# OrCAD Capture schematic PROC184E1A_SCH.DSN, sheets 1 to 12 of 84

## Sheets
1 07. PDN: title: PDN; rev: E1; note: PROC141_SCH
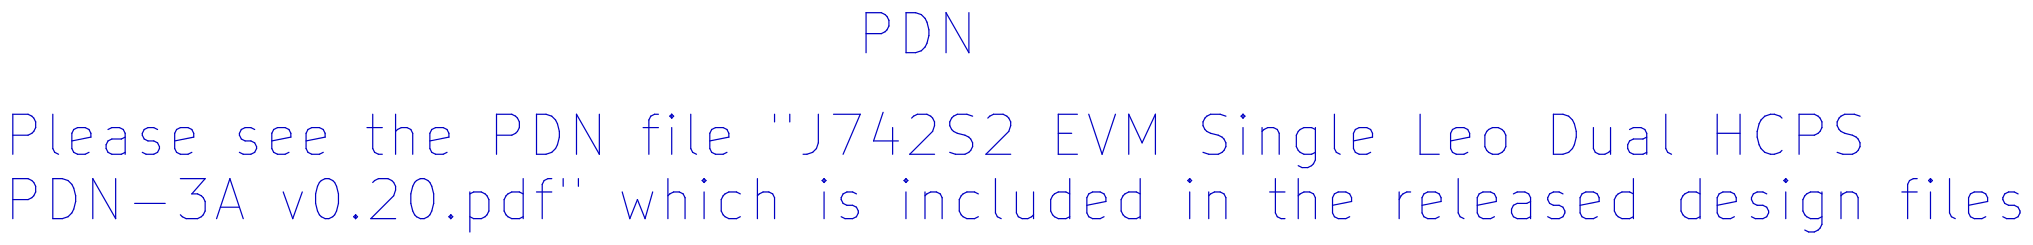
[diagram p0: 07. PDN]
2 03. REVISION HISTORY #2: title: REVISION HISTORY; note: PROC184_SCH
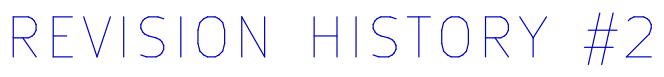
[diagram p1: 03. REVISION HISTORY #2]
3 09. I2C TABLE: title: REVISION HISTORY; note: PROC184_SCH
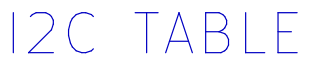
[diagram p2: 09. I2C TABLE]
4 01. TABLE OF CONTENTS: title: TABLE OF CONTENTS; note: PROC184_SCH
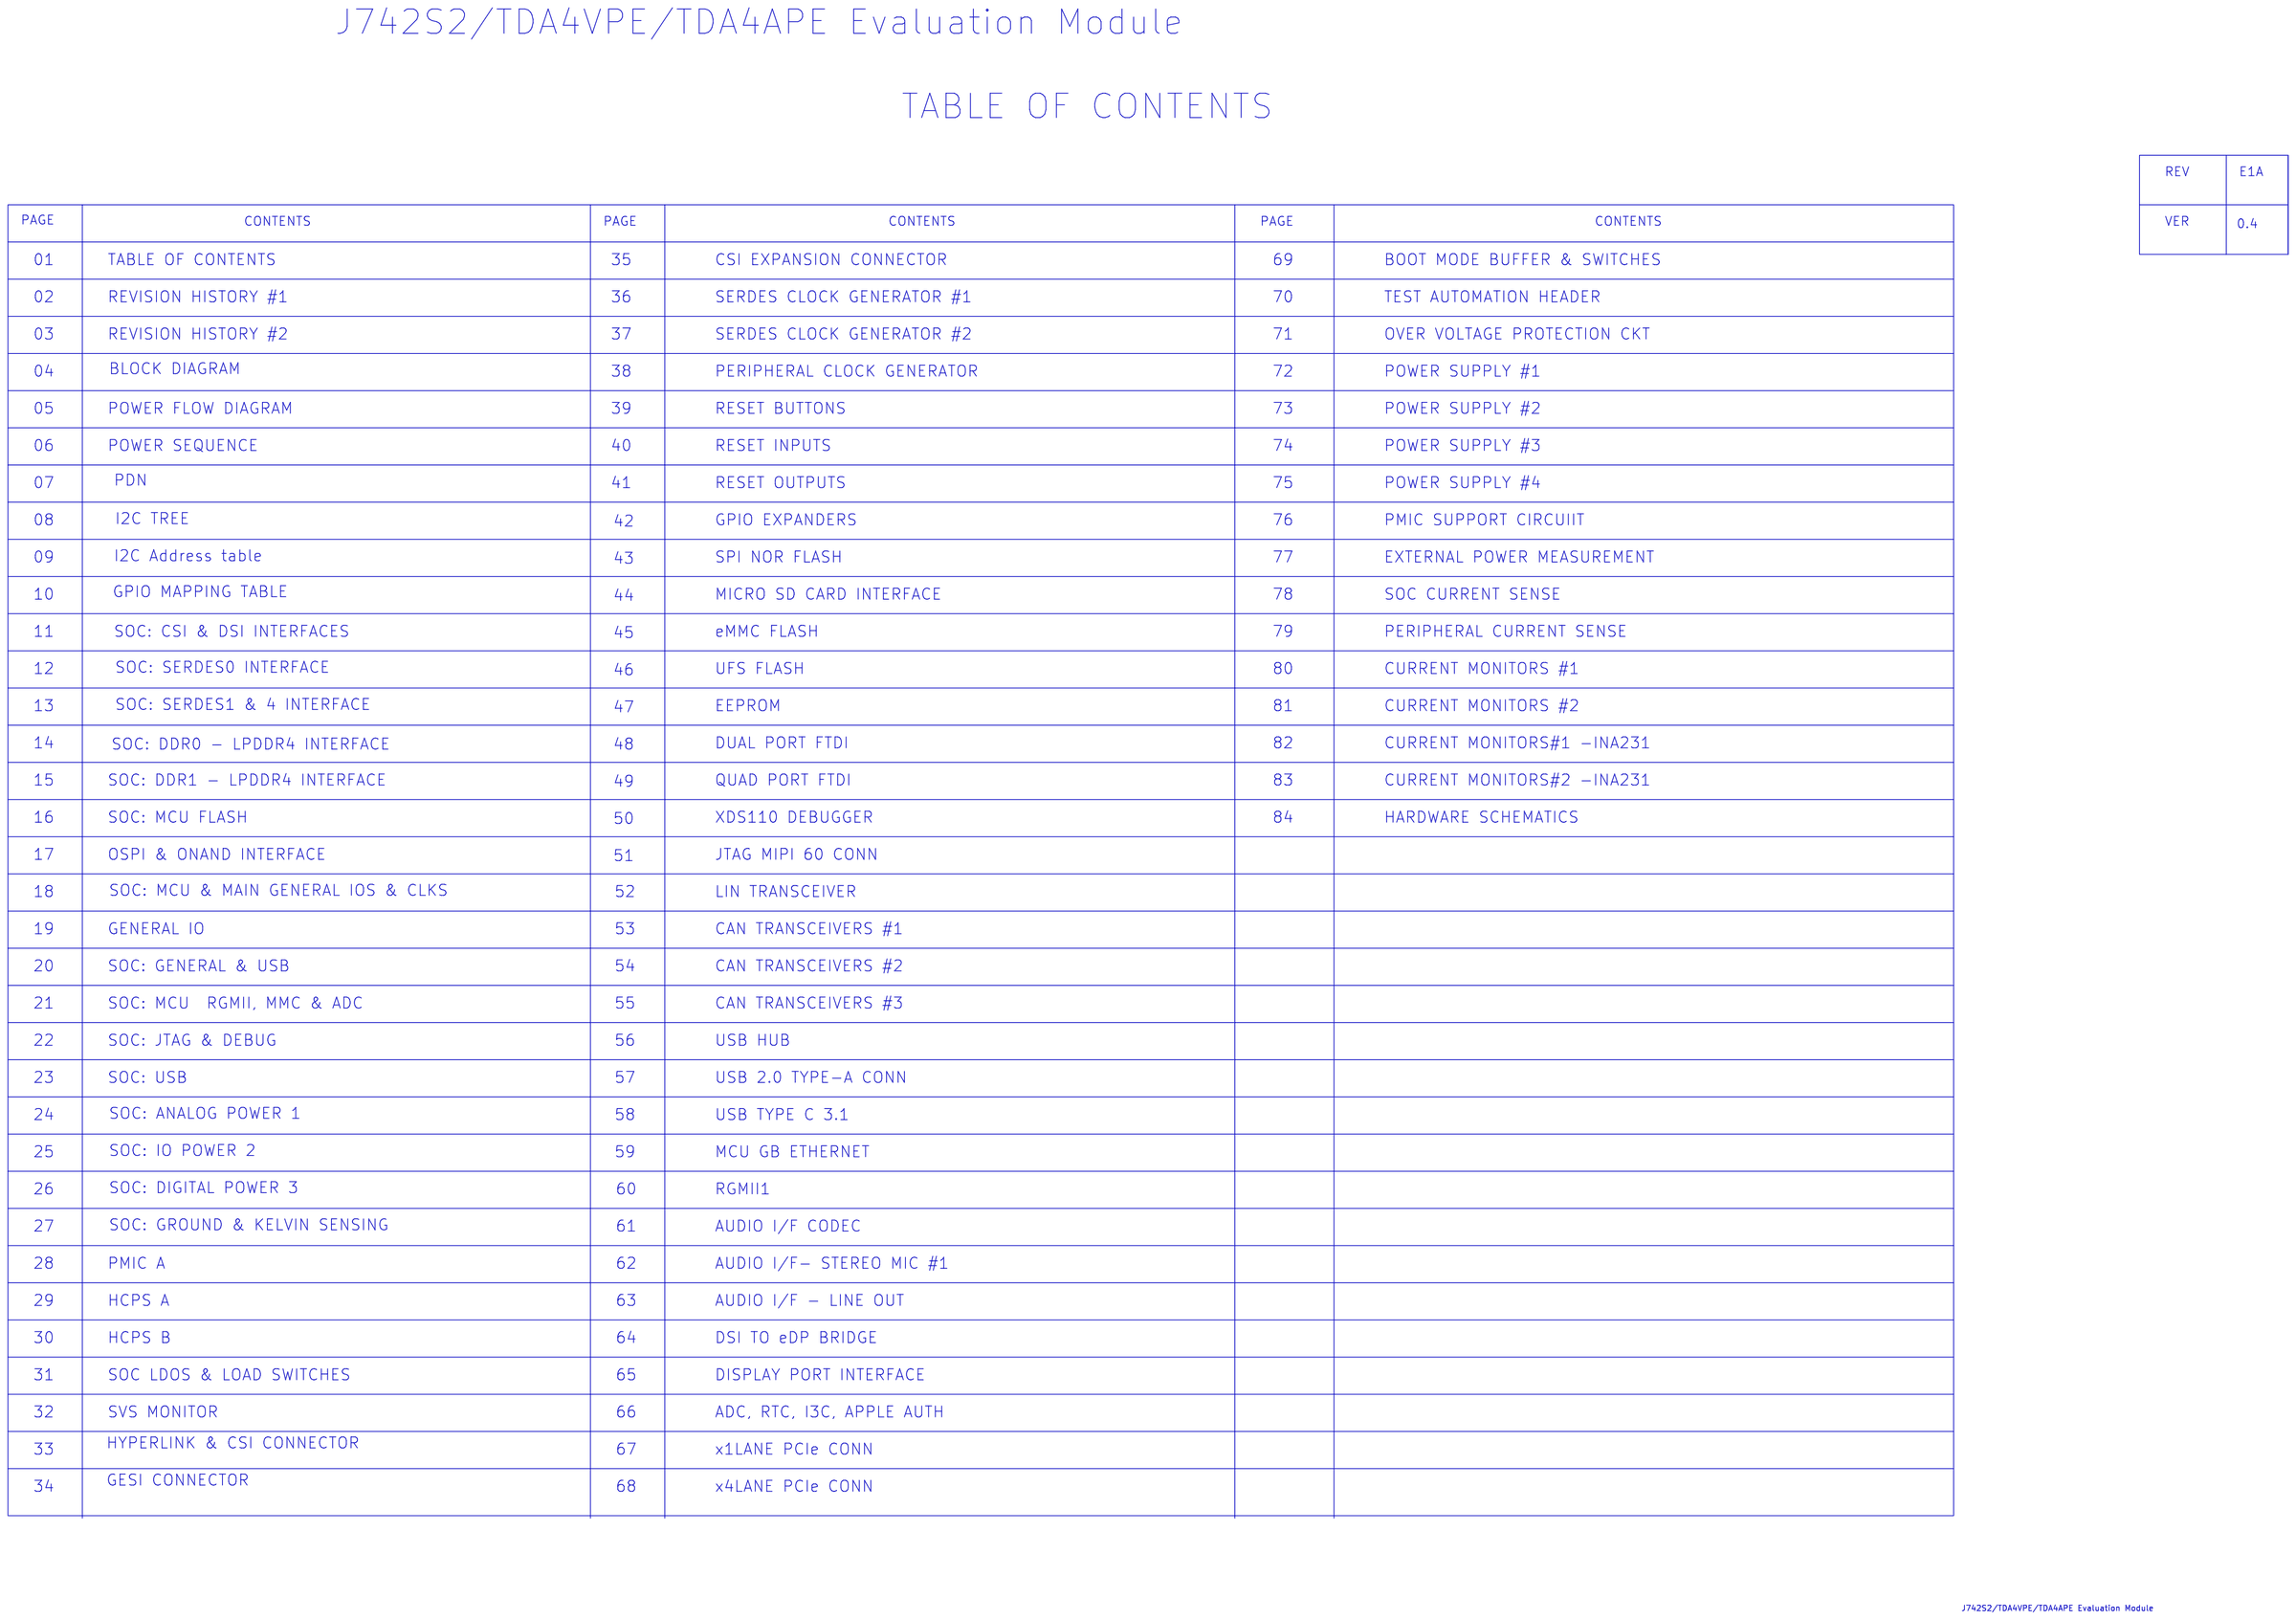
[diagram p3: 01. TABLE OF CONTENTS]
5 02. REVISION HISTORY #1: title: REVISION HISTORY; note: PROC184_SCH
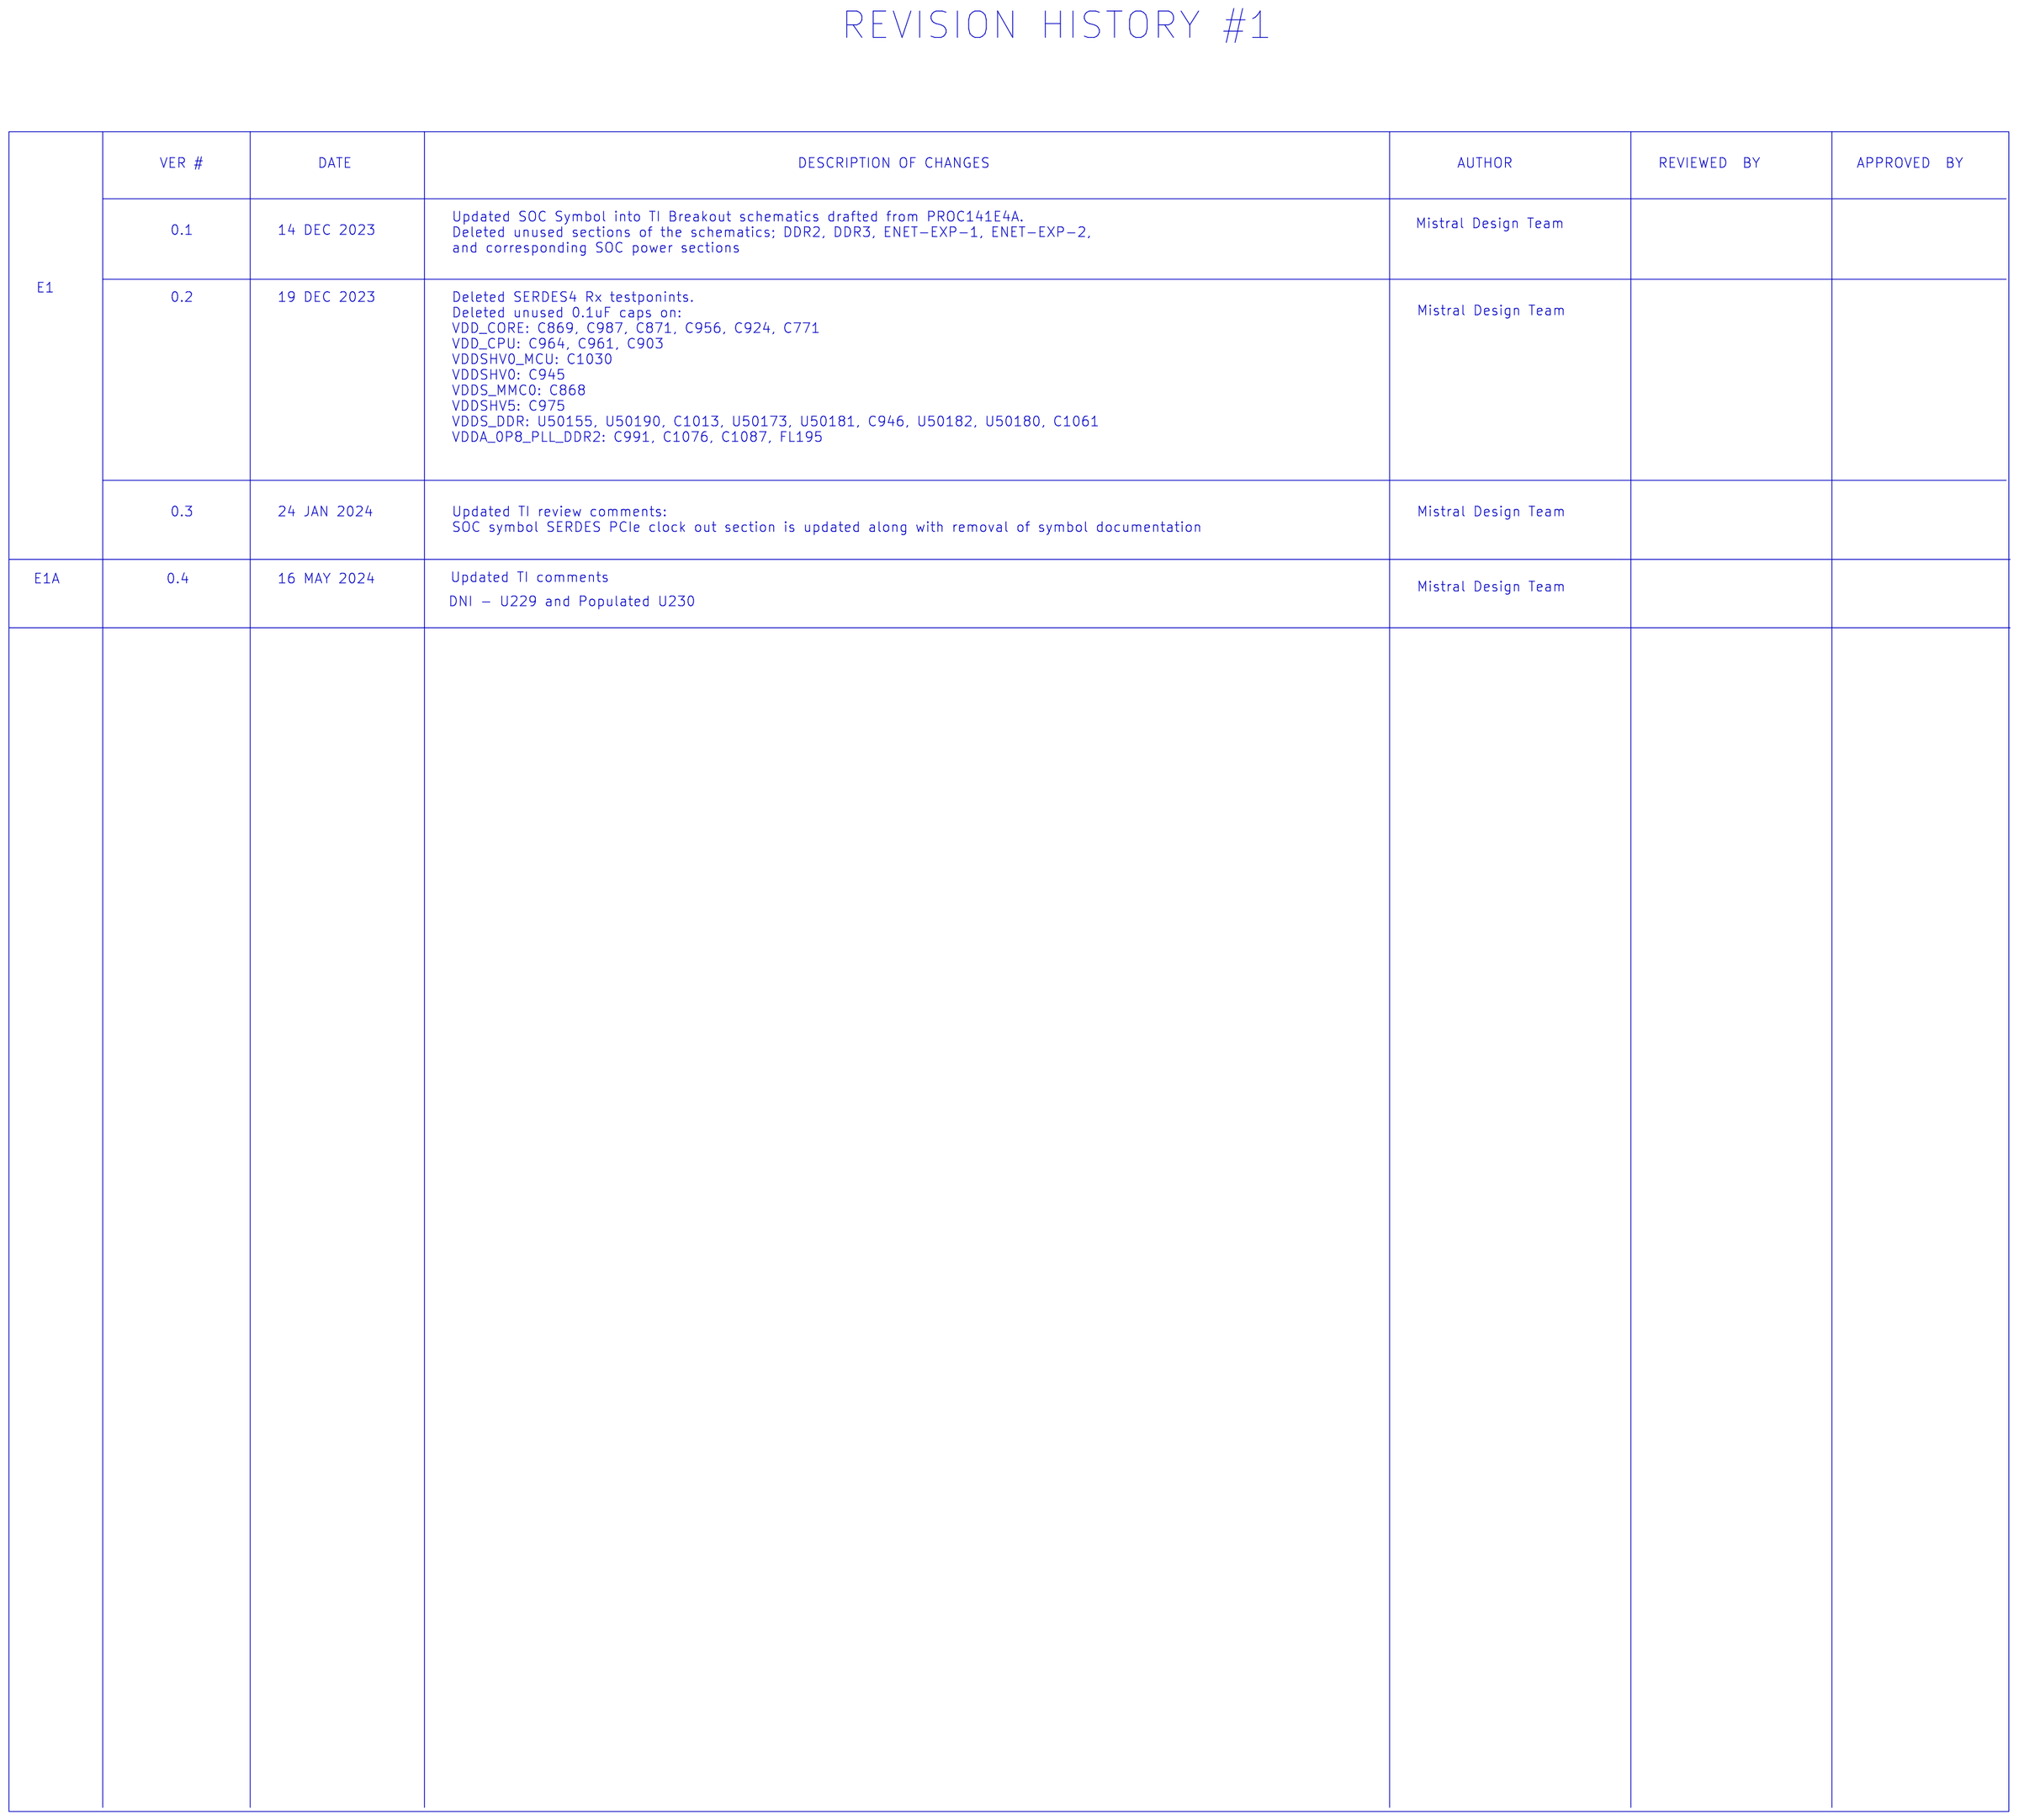
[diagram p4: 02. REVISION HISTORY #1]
6 04. BLOCK_DIAGRAM: title: BLOCK DIAGRAM; note: PROC184_SCH
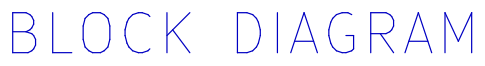
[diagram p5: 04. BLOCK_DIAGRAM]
7 05. POWER FLOW DIAGRAM: title: POWER FLOW DIAGRAM; note: PROC184_SCH
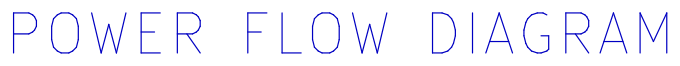
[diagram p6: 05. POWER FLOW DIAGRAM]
8 06. POWER SEQUENCE: title: POWER SEQUENCE; note: PROC184_SCH
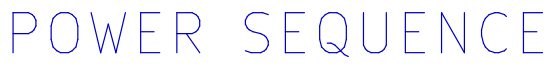
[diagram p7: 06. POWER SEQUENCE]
9 08. I2C TREE: title: I2C TREE; note: PROC184_SCH
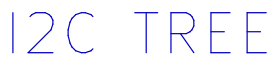
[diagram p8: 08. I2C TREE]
10 10. GPIO MAPPING TABLE: title: GPIO  EXPANDER MAP/TABLE; note: PROC184_SCH
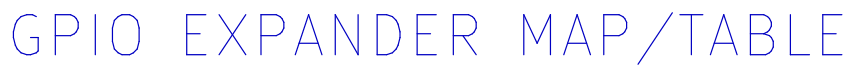
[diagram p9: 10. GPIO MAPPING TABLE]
11 11. SOC CSI & DSI IF: size C; title: CSI & DSI INTERFACE; company: TEXAS INSTRUMENTS INCORPORATED; note: PROC184_SCH
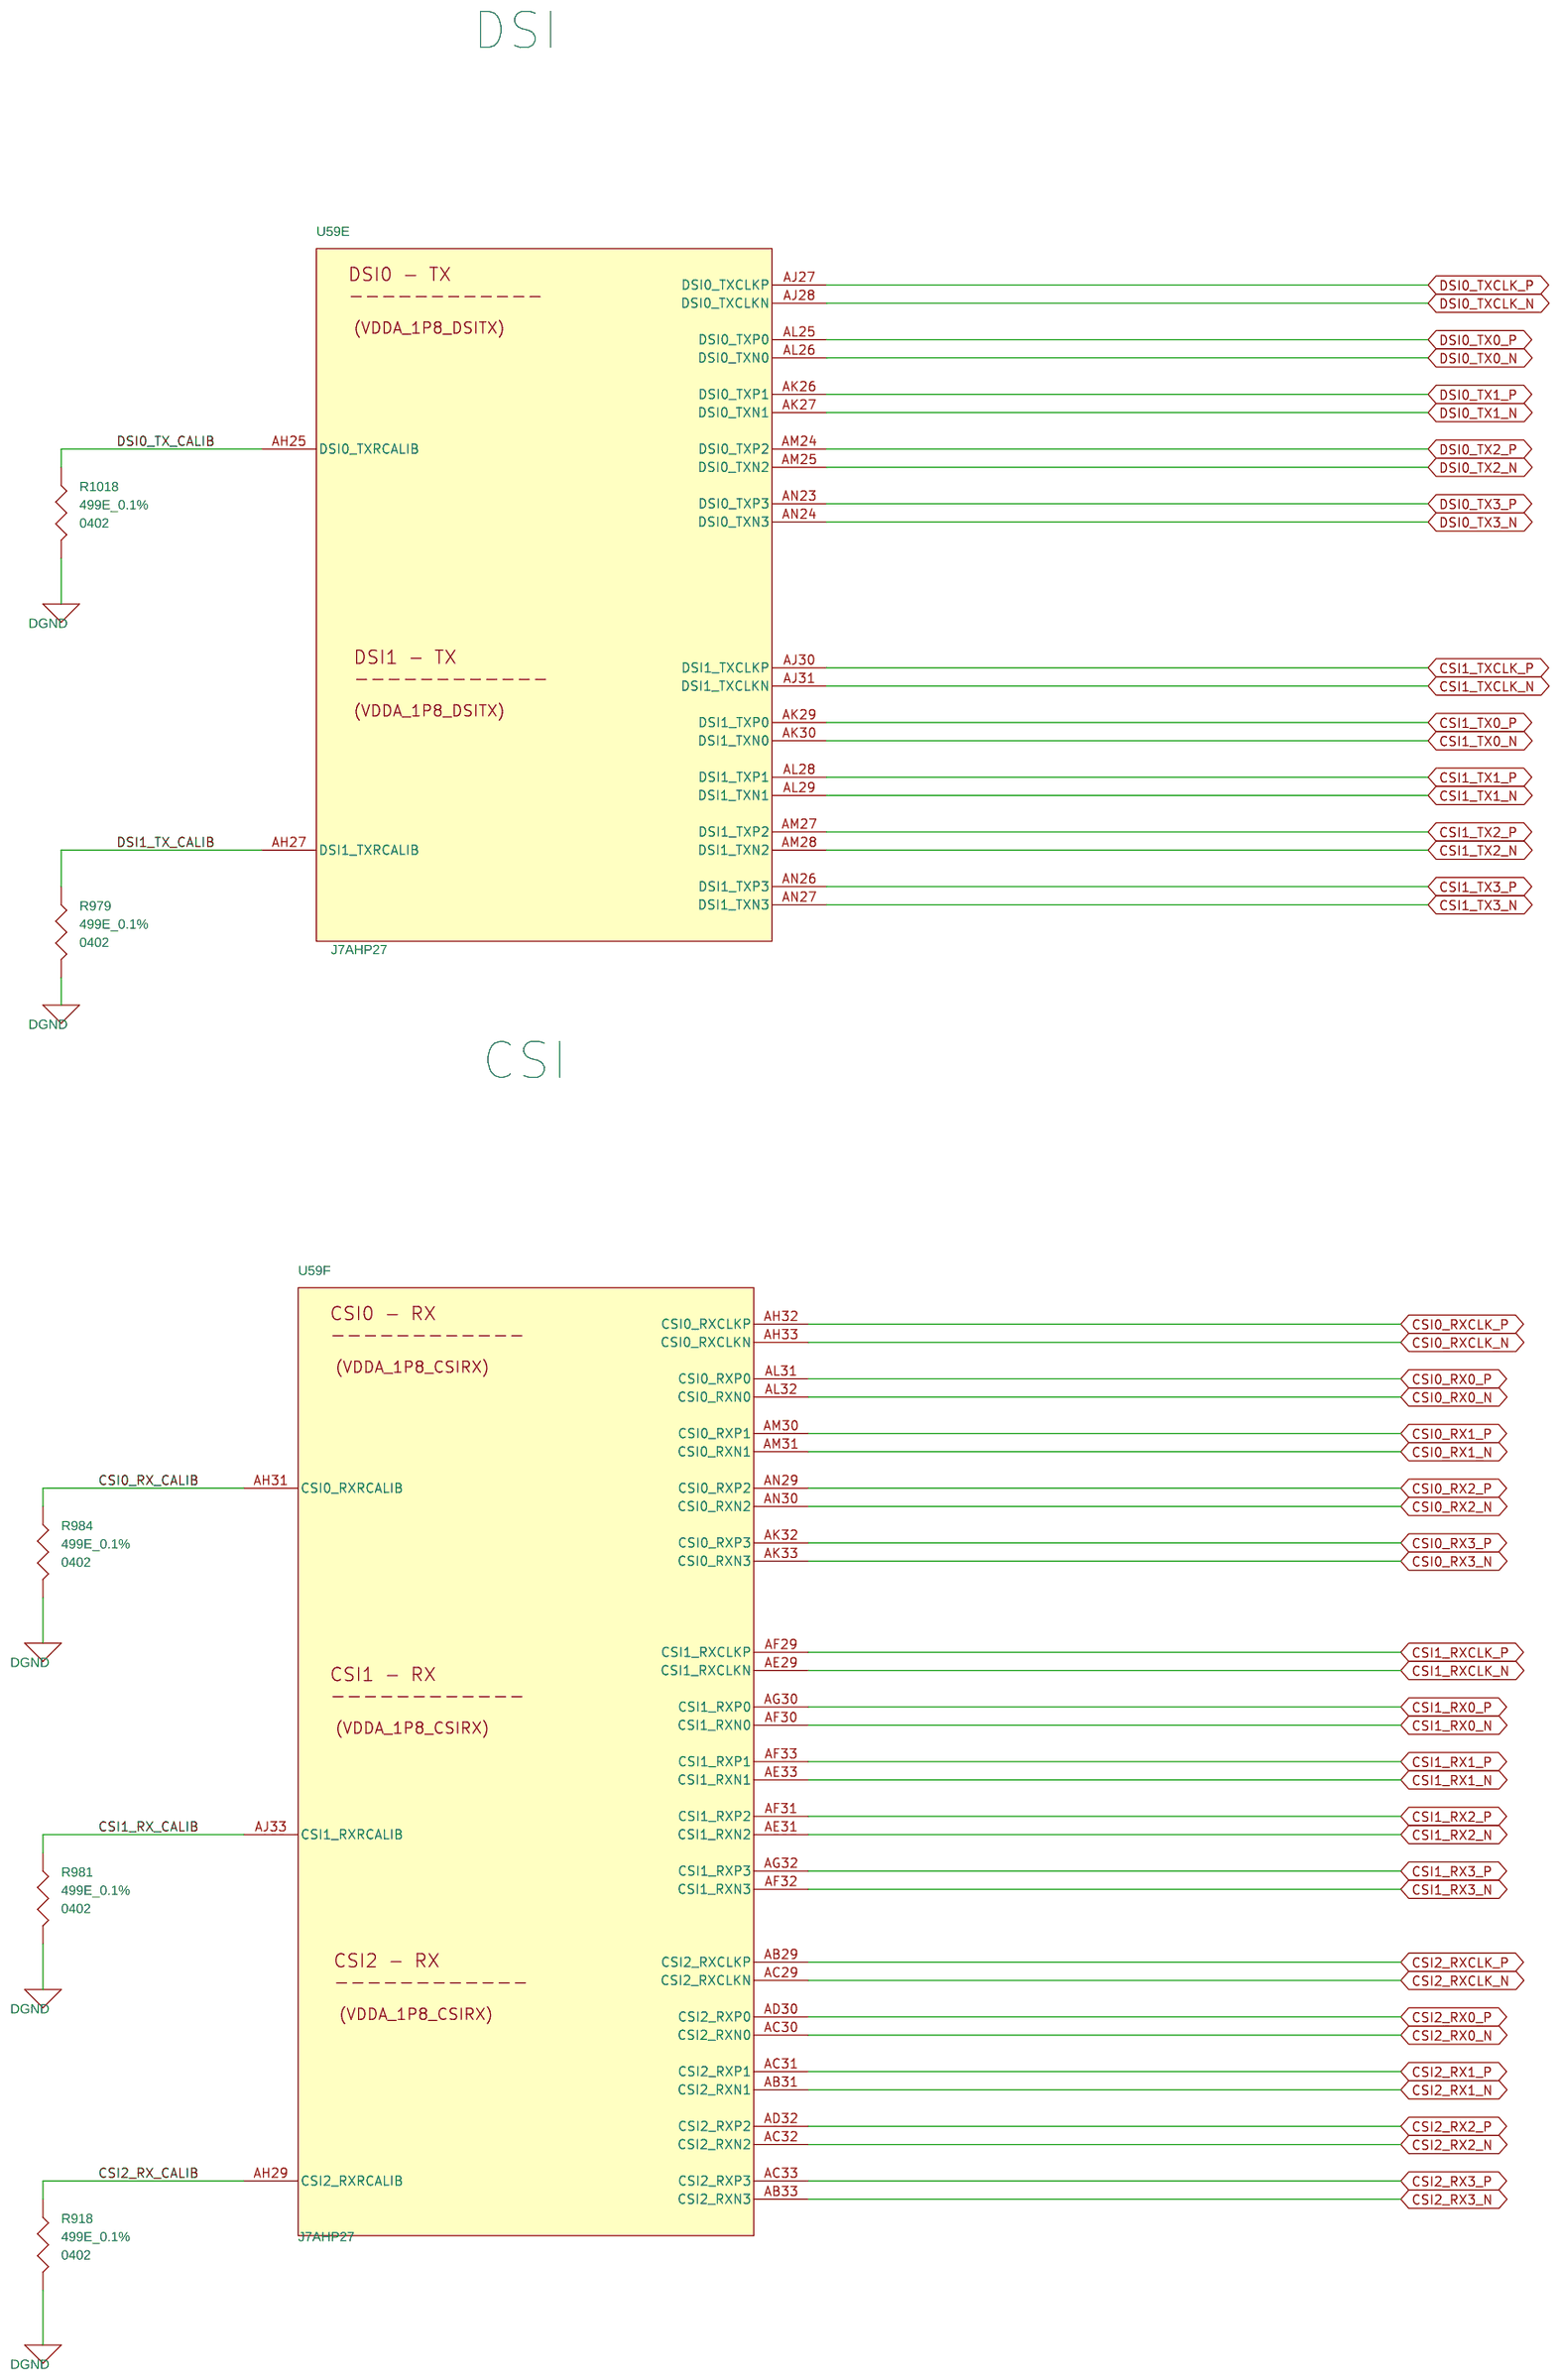
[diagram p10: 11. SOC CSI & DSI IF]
12 12. SOC SERDES0 IF: size C; title: SERDES INTERFACE; company: TEXAS INSTRUMENTS INCORPORATED; note: PROC184_SCH
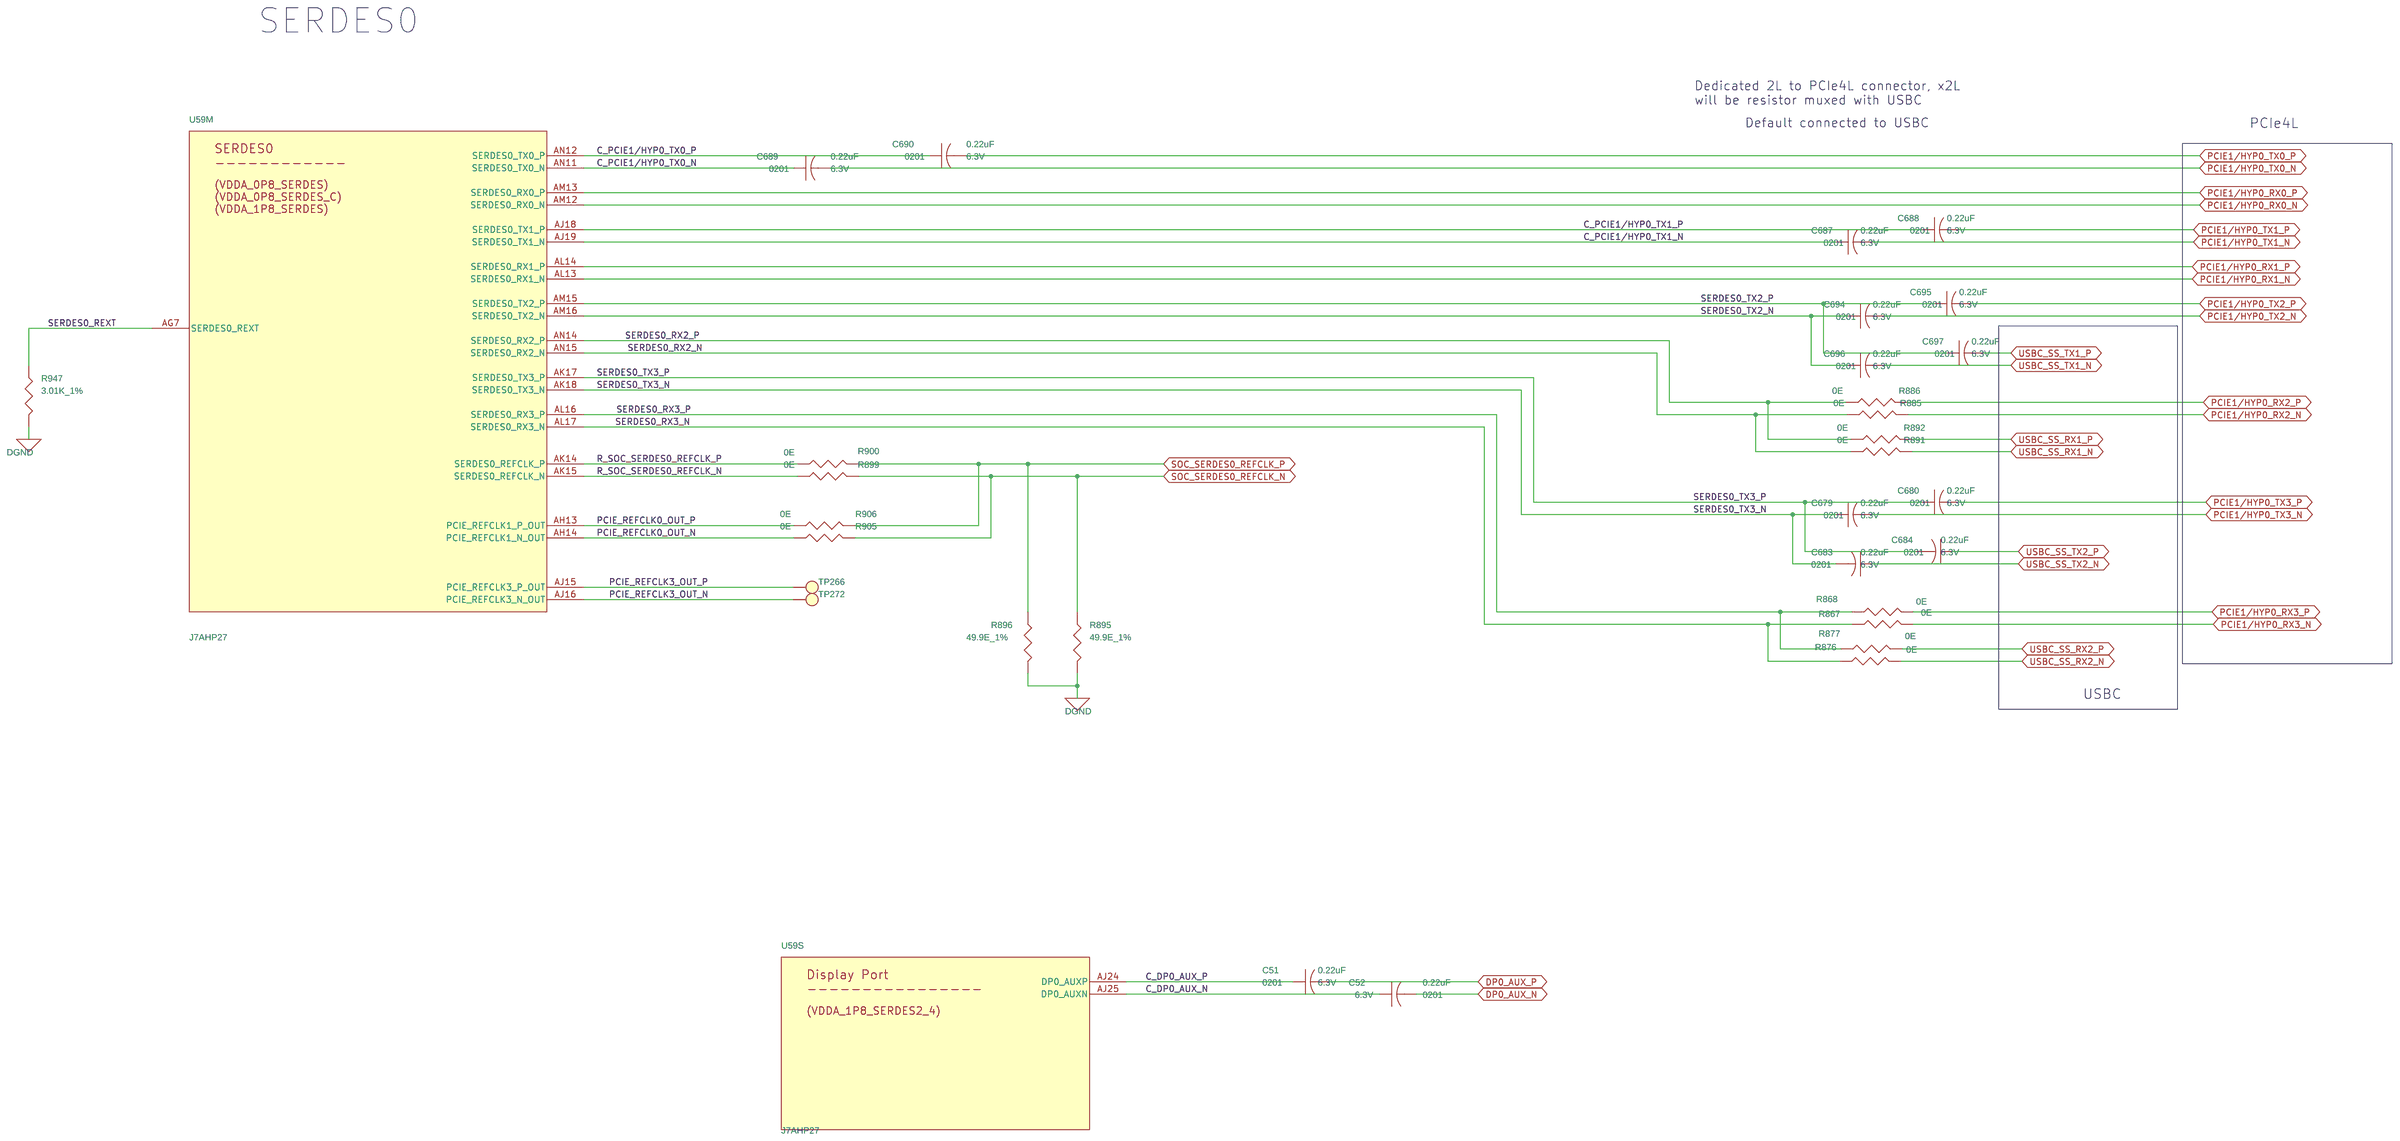
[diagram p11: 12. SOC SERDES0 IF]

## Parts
sheet 11. SOC CSI & DSI IF
R918  499E_0.1%  [RES0402_0-5]
R979  499E_0.1%  [RES0402_0-5]
R981  499E_0.1%  [RES0402_0-5]
R984  499E_0.1%  [RES0402_0-5]
R1018  499E_0.1%  [RES0402_0-5]
sheet 12. SOC SERDES0 IF
C51  0.22uF  [CAP0201_0-5]
C52  0.22uF  [CAP0201_0-5]
C679  0.22uF  [CAP0201_0-5]
C680  0.22uF  [CAP0201_0-5]
C683  0.22uF  [CAP0201_0-5]
C684  0.22uF  [CAP0201_0-5]
C687  0.22uF  [CAP0201_0-5]
C688  0.22uF  [CAP0201_0-5]
C689  0.22uF  [CAP0201_0-5]
C690  0.22uF  [CAP0201_0-5]
C694  0.22uF  [CAP0201_0-5]
C695  0.22uF  [CAP0201_0-5]
C696  0.22uF  [CAP0201_0-5]
C697  0.22uF  [CAP0201_0-5]
R867  0E  [RES0201_0-5]
R868  0E  [RES0201_0-5]
R876  0E  [RES0201_0-5]
R877  0E  [RES0201_0-5]
R885  0E  [RES0201_0-5]
R886  0E  [RES0201_0-5]
R891  0E  [RES0201_0-5]
R892  0E  [RES0201_0-5]
R895  49.9E_1%  [RES0402_0-5]
R896  49.9E_1%  [RES0402_0-5]
R899  0E  [RES0201_0-5]
R900  0E  [RES0201_0-5]
R905  0E  [RES0201_0-5]
R906  0E  [RES0201_0-5]
R947  3.01K_1%  [RES0201_0-5]
TP266  TP30_SMD  [TP30_SMD]
TP272  TP30_SMD  [TP30_SMD]
sheet 15. SOC EMIF1 & LPDDR4
U59  J7AHP27  [BGASKT-33X33-1063-P8MM]  (sections A,B,C,D,E,F,G,H,I,J,K,L,M,N,O,P,Q,R,S,T,U,V,W)

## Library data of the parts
R918 R979 R981 R984 R1018 = RESISTOR: RES 499E 1/16W 0.1% 0402; Chkd/date: ALVY/200921; Crtd /date: MANIRAJA/200921; Custom_Duty: 15%; Customs_HS_Code: 85332119; Distributor_name: DIGIKEY; Distributor_part_number: YAG1440CT-ND; Footprint Path: Y:\MIS_DATABASE\Library\ALTIUM_TOOL\PCB_FOOTPRINTS\Altium_Footprint_Lib.PcbLib; Height: 0.35MM; Library Path: Y:\MIS_DATABASE\Library\ALTIUM_TOOL\SCHEMATICS_PARTS\MS_DISCRETE_Library.schlib; Manufacturer: YAGEO AMERICA; Mfr_name: YAGEO AMERICA; Mfr_part_number: RT0402BRD07499RL; Mistral Part No: 110021020006-R; Package: 0402; Part_type: RESISTORS\FIXED; Project: TI_AM62x SKEVM_BRD; RoHS: RoHS; Temperature: -55°C+155°C; Tolerance: 0.1%; Voltage: NA; Wattage: 1/16W; Weight: 0.65mg; Datasheet: Y:\MIS_DATABASE\DATASHEETS\RESISTORS\YAGEO_RT-SERIES.PDF
C51 C52 C679 C680 C683 C684 C687-C690 C694-C697 = CAP: CAP CERAMIC 0.22uF 6.3V 10% X6S AUTO 0201; Chkd/date: MANIRAJA/220219; Crtd /date: ALVY/220219; Custom_Duty: 15%; Customs_HS_Code: 85322990; Distributor_name: DIGIKEY; Distributor_part_number: 490-12230-1-ND; Footprint Path: Y:\MIS_DATABASE\Library\ALTIUM_TOOL\PCB_FOOTPRINTS\Altium_Footprint_Lib.PcbLib; Height: 0.33MM; Library Path: Y:\MIS_DATABASE\Library\ALTIUM_TOOL\SCHEMATICS_PARTS\MS_DISCRETE_Library.schlib; Manufacturer: MURATA; Mfr_name: MURATA; Mfr_part_number: GRT033C80J224KE01D; Mistral Part No: 120019020011-R; Package: 0201; Part_type: CAPACITORS\CERAMIC; Project: TI_J7ES_EVM_SOM; RoHS: RoHS; Temperature: -55°C+105°C; Tolerance: 10%; Voltage: 6.3V; Wattage: NA; Weight: 0.17mg; Datasheet: Y:\MIS_DATABASE\DATASHEETS\CAPACITORS\MURATA-GCM-SER.PDF
R867 R868 R876 R877 R885 R886 R891 R892 R899 R900 R905 R906 = RESISTOR: RES 0E 1/20W 5% 0201; Chkd/date: NAVEED/301214; Crtd /date: MUDDU/120710; Custom_Duty: 15%; Customs_HS_Code: 85332119; Distributor_name: DIGIKEY; Distributor_part_number: 311-0.0NCT-ND; Footprint Path: Y:\MIS_DATABASE\Library\ALTIUM_TOOL\PCB_FOOTPRINTS\Altium_Footprint_Lib.PcbLib; Height: 0.26MM; Library Path: Y:\MIS_DATABASE\Library\ALTIUM_TOOL\SCHEMATICS_PARTS\MS_DISCRETE_Library.schlib; Manufacturer: YAGEO AMERICA; Mfr_name: YAGEO AMERICA; Mfr_part_number: RC0201JR-070RL; Mistral Part No: 110010070067-R; Package: 0201; Part_type: RESISTORS\FIXED; Project: PB_BUGBASE; RoHS: RoHS; Temperature: -55°C+125°C; Tolerance: 5%; Voltage: NA; Wattage: 1/20W; Weight: 0.17mg; Datasheet: Y:\MIS_DATABASE\DATASHEETS\RESISTORS\RCXXXXL-SER_MAR18.PDF
R895 R896 = RESISTOR: RES 49.9E 1/10W 1% 0402; Chkd/date: VASANTHA/201216; Crtd /date: MAZHAR/201005; Custom_Duty: 15%; Customs_HS_Code: 85332119; Distributor_name: DIGIKEY; Distributor_part_number: P49.9LCT-ND; Footprint Path: Y:\MIS_DATABASE\Library\ALTIUM_TOOL\PCB_FOOTPRINTS\Altium_Footprint_Lib.PcbLib; Height: 0.40MM; Library Path: Y:\MIS_DATABASE\Library\ALTIUM_TOOL\SCHEMATICS_PARTS\MS_DISCRETE_Library.schlib; Manufacturer: PANASONIC-ECG; Mfr_name: PANASONIC-ECG; Mfr_part_number: ERJ-2RKF49R9X; Mistral Part No: 110009030897-R; Package: 0402; Part_type: RESISTORS\FIXED; Project: RED EYE; RoHS: RoHS; Temperature: -55°C+155°C; Tolerance: 1%; Voltage: NA; Wattage: 1/10W; Weight: 0.8mg; Datasheet: Y:\MIS_DATABASE\DATASHEETS\RESISTORS\PAN-ERJSER_NOV17.PDF
R947 = RESISTOR: RES 3.01K 1/20W 1% 0201; Chkd/date: MANIRAJA/160519; Crtd /date: ALVY/160519; Custom_Duty: 15%; Customs_HS_Code: 85332119; Distributor_name: DIGIKEY; Distributor_part_number: P122916CT-ND; Footprint Path: Y:\MIS_DATABASE\Library\ALTIUM_TOOL\PCB_FOOTPRINTS\Altium_Footprint_Lib.PcbLib; Height: 0.26MM; Library Path: Y:\MIS_DATABASE\Library\ALTIUM_TOOL\SCHEMATICS_PARTS\MS_DISCRETE_Library.schlib; Manufacturer: PANASONIC-ECG; Mfr_name: PANASONIC-ECG; Mfr_part_number: ERJ-1GNF3011C; Mistral Part No: 110015080044-R; Package: 0201; Part_type: RESISTORS\FIXED; Project: J7ES_SOM_DUAL-LEO_PMIC; RoHS: RoHS; Temperature: -55°C+125°C; Tolerance: 1%; Voltage: NA; Wattage: 1/20W; Weight: 0.15mg; Datasheet: Y:\MIS_DATABASE\DATASHEETS\RESISTORS\PAN-ERJSER_NOV17.PDF
TP266 TP272 = TESTPOINT: TESTPOINT CIR 30 SMD; Chkd/date: SHREESHAIL/171006; Crtd /date: MAZHAR/171006; Custom_Duty: NA; Customs_HS_Code: NA; Distributor_name: NA; Distributor_part_number: NA; Footprint Path: Y:\MIS_DATABASE\Library\ALTIUM_TOOL\PCB_FOOTPRINTS\Altium_Footprint_Lib.PcbLib; Height: NA; Library Path: Y:\MIS_DATABASE\Library\ALTIUM_TOOL\SCHEMATICS_PARTS\MS_DISCRETE_Library.schlib; MECHANICAL 3D STEP FILE: NA; Manufacturer: LOCAL; Mfr_name: LOCAL; Mistral Part No: 130009030930; Package: SMD; Project: BT MODULE_CSRBC04; RoHS: NA; Temperature: NA; Tolerance: NA; Voltage: NA; Wattage: NA; Weight: NA; Datasheet: NA
U59 = J7AHP27SoC_BGA1063: IC J7AHP27 SoC EVM MICROPROCESSOR BGA1063; Chkd/date: PRADEEP/181223; Crtd /date: TAMILARASU/111223; Custom_Duty: 15%; Customs_HS_Code: 85423100; Distributor_name: NA; Distributor_part_number: NA; Footprint Path: Y:\MIS_DATABASE\Library\ALTIUM_TOOL\PCB_FOOTPRINTS\Altium_Footprint_Lib.PcbLib; Height: 3.30MM; Library Path: Y:\MIS_DATABASE\Library\ALTIUM_TOOL\SCHEMATICS_PARTS\MS_MICROPROCESSOR_Library.schlib; Mfr_name: NA; Mistral Part No: 141223120002; Package: BGA1063; Part_type: ICS\DIGITAL\MICROPROCESSOR; Project: J7AHP27_V08 SOC; RoHS: NA; Temperature: NA; Tolerance: NA; Voltage: NA; Wattage: NA; Weight: NA; Datasheet: Y:\MIS_DATABASE\DATASHEETS\ICS\DIGITAL\MICROCONTROLLER\J7AHP27.PDF

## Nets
DGND: R895.2 R896.2 R918.2 R947.2 R979.2 R981.2 R984.2 R1018.2 ; also on sheet 13 14 15 16 17 18 20 21 22 23 24 25 26 27 28 29 30 31 32 33 34 35 36 37 38 39 40 41 42 43 44 45 46 47 48 49 50 51 52 53 54 55 56 57 58 59 60 61 62 63 64 65 66 67 68 69 70 71 72 73 76 77 78 79 81 82 83 84
C_DP0_AUX_N: C52.1 U59.AJ25(DP0_AUXN)
C_DP0_AUX_P: C51.1 U59.AJ24(DP0_AUXP)
C_PCIE1/HYP0_TX0_N: C689.1 U59.AN11(SERDES0_TX0_N)
C_PCIE1/HYP0_TX0_P: C690.1 U59.AN12(SERDES0_TX0_P)
C_PCIE1/HYP0_TX1_N: C687.1 U59.AJ19(SERDES0_TX1_N)
C_PCIE1/HYP0_TX1_P: C688.1 U59.AJ18(SERDES0_TX1_P)
CSI0_RX0_N: U59.AL32(CSI0_RXN0) ; also on sheet 31
CSI0_RX0_P: U59.AL31(CSI0_RXP0) ; also on sheet 31
CSI0_RX1_N: U59.AM31(CSI0_RXN1) ; also on sheet 31
CSI0_RX1_P: U59.AM30(CSI0_RXP1) ; also on sheet 31
CSI0_RX2_N: U59.AN30(CSI0_RXN2) ; also on sheet 31
CSI0_RX2_P: U59.AN29(CSI0_RXP2) ; also on sheet 31
CSI0_RX3_N: U59.AK33(CSI0_RXN3) ; also on sheet 31
CSI0_RX3_P: U59.AK32(CSI0_RXP3) ; also on sheet 31
CSI0_RX_CALIB: R984.1 U59.AH31(CSI0_RXRCALIB)
CSI0_RXCLK_N: U59.AH33(CSI0_RXCLKN) ; also on sheet 31
CSI0_RXCLK_P: U59.AH32(CSI0_RXCLKP) ; also on sheet 31
CSI1_RX0_N: U59.AF30(CSI1_RXN0) ; also on sheet 31
CSI1_RX0_P: U59.AG30(CSI1_RXP0) ; also on sheet 31
CSI1_RX1_N: U59.AE33(CSI1_RXN1) ; also on sheet 31
CSI1_RX1_P: U59.AF33(CSI1_RXP1) ; also on sheet 31
CSI1_RX2_N: U59.AE31(CSI1_RXN2) ; also on sheet 31
CSI1_RX2_P: U59.AF31(CSI1_RXP2) ; also on sheet 31
CSI1_RX3_N: U59.AF32(CSI1_RXN3) ; also on sheet 31
CSI1_RX3_P: U59.AG32(CSI1_RXP3) ; also on sheet 31
CSI1_RX_CALIB: R981.1 U59.AJ33(CSI1_RXRCALIB)
CSI1_RXCLK_N: U59.AE29(CSI1_RXCLKN) ; also on sheet 31
CSI1_RXCLK_P: U59.AF29(CSI1_RXCLKP) ; also on sheet 31
CSI1_TX0_N: U59.AK30(DSI1_TXN0) ; also on sheet 29
CSI1_TX0_P: U59.AK29(DSI1_TXP0) ; also on sheet 29
CSI1_TX1_N: U59.AL29(DSI1_TXN1) ; also on sheet 29
CSI1_TX1_P: U59.AL28(DSI1_TXP1) ; also on sheet 29
CSI1_TX2_N: U59.AM28(DSI1_TXN2) ; also on sheet 29
CSI1_TX2_P: U59.AM27(DSI1_TXP2) ; also on sheet 29
CSI1_TX3_N: U59.AN27(DSI1_TXN3) ; also on sheet 29
CSI1_TX3_P: U59.AN26(DSI1_TXP3) ; also on sheet 29
CSI1_TXCLK_N: U59.AJ31(DSI1_TXCLKN) ; also on sheet 29
CSI1_TXCLK_P: U59.AJ30(DSI1_TXCLKP) ; also on sheet 29
CSI2_RX0_N: U59.AC30(CSI2_RXN0) ; also on sheet 31
CSI2_RX0_P: U59.AD30(CSI2_RXP0) ; also on sheet 31
CSI2_RX1_N: U59.AB31(CSI2_RXN1) ; also on sheet 31
CSI2_RX1_P: U59.AC31(CSI2_RXP1) ; also on sheet 31
CSI2_RX2_N: U59.AC32(CSI2_RXN2) ; also on sheet 31
CSI2_RX2_P: U59.AD32(CSI2_RXP2) ; also on sheet 31
CSI2_RX3_N: U59.AB33(CSI2_RXN3) ; also on sheet 31
CSI2_RX3_P: U59.AC33(CSI2_RXP3) ; also on sheet 31
CSI2_RX_CALIB: R918.1 U59.AH29(CSI2_RXRCALIB)
CSI2_RXCLK_N: U59.AC29(CSI2_RXCLKN) ; also on sheet 31
CSI2_RXCLK_P: U59.AB29(CSI2_RXCLKP) ; also on sheet 31
DP0_AUX_N: C52.2 ; also on sheet 57
DP0_AUX_P: C51.2 ; also on sheet 57
DSI0_TX0_N: U59.AL26(DSI0_TXN0) ; also on sheet 61
DSI0_TX0_P: U59.AL25(DSI0_TXP0) ; also on sheet 61
DSI0_TX1_N: U59.AK27(DSI0_TXN1) ; also on sheet 61
DSI0_TX1_P: U59.AK26(DSI0_TXP1) ; also on sheet 61
DSI0_TX2_N: U59.AM25(DSI0_TXN2) ; also on sheet 61
DSI0_TX2_P: U59.AM24(DSI0_TXP2) ; also on sheet 61
DSI0_TX3_N: U59.AN24(DSI0_TXN3) ; also on sheet 61
DSI0_TX3_P: U59.AN23(DSI0_TXP3) ; also on sheet 61
DSI0_TX_CALIB: R1018.1 U59.AH25(DSI0_TXRCALIB)
DSI0_TXCLK_N: U59.AJ28(DSI0_TXCLKN) ; also on sheet 61
DSI0_TXCLK_P: U59.AJ27(DSI0_TXCLKP) ; also on sheet 61
DSI1_TX_CALIB: R979.1 U59.AH27(DSI1_TXRCALIB)
PCIE1/HYP0_RX0_N: U59.AM12(SERDES0_RX0_N) ; also on sheet 60
PCIE1/HYP0_RX0_P: U59.AM13(SERDES0_RX0_P) ; also on sheet 60
PCIE1/HYP0_RX1_N: U59.AL13(SERDES0_RX1_N) ; also on sheet 60
PCIE1/HYP0_RX1_P: U59.AL14(SERDES0_RX1_P) ; also on sheet 60
PCIE1/HYP0_RX2_N: R885.1 ; also on sheet 60
PCIE1/HYP0_RX2_P: R886.1 ; also on sheet 60
PCIE1/HYP0_RX3_N: R867.2 ; also on sheet 60
PCIE1/HYP0_RX3_P: R868.2 ; also on sheet 60
PCIE1/HYP0_TX0_N: C689.2 ; also on sheet 60
PCIE1/HYP0_TX0_P: C690.2 ; also on sheet 60
PCIE1/HYP0_TX1_N: C687.2 ; also on sheet 60
PCIE1/HYP0_TX1_P: C688.2 ; also on sheet 60
PCIE1/HYP0_TX2_N: C694.2 ; also on sheet 60
PCIE1/HYP0_TX2_P: C695.2 ; also on sheet 60
PCIE1/HYP0_TX3_N: C679.2 ; also on sheet 60
PCIE1/HYP0_TX3_P: C680.2 ; also on sheet 60
PCIE_REFCLK0_OUT_N: R905.2 U59.AH14(PCIE_REFCLK1_N_OUT)
PCIE_REFCLK0_OUT_P: R906.2 U59.AH13(PCIE_REFCLK1_P_OUT)
PCIE_REFCLK3_OUT_N: TP272.1(TP) U59.AJ16(PCIE_REFCLK3_N_OUT)
PCIE_REFCLK3_OUT_P: TP266.1(TP) U59.AJ15(PCIE_REFCLK3_P_OUT)
R_SOC_SERDES0_REFCLK_N: R899.2 U59.AK15(SERDES0_REFCLK_N)
R_SOC_SERDES0_REFCLK_P: R900.2 U59.AK14(SERDES0_REFCLK_P)
SERDES0_REXT: R947.1 U59.AG7(SERDES0_REXT)
SERDES0_RX2_N: R885.2 R891.2 U59.AN15(SERDES0_RX2_N)
SERDES0_RX2_P: R886.2 R892.2 U59.AN14(SERDES0_RX2_P)
SERDES0_RX3_N: R867.1 R876.1 U59.AL17(SERDES0_RX3_N)
SERDES0_RX3_P: R868.1 R877.1 U59.AL16(SERDES0_RX3_P)
SERDES0_TX2_N: C694.1 C696.1 U59.AM16(SERDES0_TX2_N)
SERDES0_TX2_P: C695.1 C697.1 U59.AM15(SERDES0_TX2_P)
SERDES0_TX3_N: C679.1 C683.2 U59.AK18(SERDES0_TX3_N)
SERDES0_TX3_P: C680.1 C684.2 U59.AK17(SERDES0_TX3_P)
SOC_SERDES0_REFCLK_N: R895.1 R899.1 R905.1 ; also on sheet 60
SOC_SERDES0_REFCLK_P: R896.1 R900.1 R906.1 ; also on sheet 60
USBC_SS_RX1_N: R891.1 ; also on sheet 53
USBC_SS_RX1_P: R892.1 ; also on sheet 53
USBC_SS_RX2_N: R876.2 ; also on sheet 53
USBC_SS_RX2_P: R877.2 ; also on sheet 53
USBC_SS_TX1_N: C696.2 ; also on sheet 53
USBC_SS_TX1_P: C697.2 ; also on sheet 53
USBC_SS_TX2_N: C683.1 ; also on sheet 53
USBC_SS_TX2_P: C684.1 ; also on sheet 53

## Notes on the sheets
sheet 1
- PDN
- Please see the PDN file "J742S2 EVM Single Leo Dual HCPS
  PDN-3A v0.20.pdf" which is included in the released design files
sheet 2
- REVISION HISTORY #2
sheet 3
- I2C TABLE
sheet 4
- J742S2/TDA4VPE/TDA4APE Evaluation Module
- TABLE OF CONTENTS
- REV
- E1A
- PAGE
- CONTENTS
- PAGE
- CONTENTS
- PAGE
- CONTENTS
- VER
- 0.4
- 01
- TABLE OF CONTENTS
- 35
- CSI EXPANSION CONNECTOR
- 69
- BOOT MODE BUFFER & SWITCHES
- 02
- REVISION HISTORY #1
- 36
- SERDES CLOCK GENERATOR #1
- 70
- TEST AUTOMATION HEADER
- 03
- REVISION HISTORY #2
- 37
- SERDES CLOCK GENERATOR #2
- 71
- OVER VOLTAGE PROTECTION CKT
- 04
- BLOCK DIAGRAM
- 38
- PERIPHERAL CLOCK GENERATOR
- 72
- POWER SUPPLY #1
- 05
- POWER FLOW DIAGRAM
- 39
- RESET BUTTONS
- 73
- POWER SUPPLY #2
- 06
- POWER SEQUENCE
- 40
- RESET INPUTS
- 74
- POWER SUPPLY #3
- 07
- PDN
- 41
- RESET OUTPUTS
- 75
- POWER SUPPLY #4
- 08
- I2C TREE
- 42
- GPIO EXPANDERS
- 76
- PMIC SUPPORT CIRCUIIT
- 09
- I2C Address table
- 43
- SPI NOR FLASH
- 77
- EXTERNAL POWER MEASUREMENT
- 10
- GPIO MAPPING TABLE
- 44
- MICRO SD CARD INTERFACE
- 78
- SOC CURRENT SENSE
- 11
- SOC: CSI & DSI INTERFACES
- eMMC FLASH
- 79
- PERIPHERAL CURRENT SENSE
- 45
- 12
- SOC: SERDES0 INTERFACE
- 46
- UFS FLASH
- 80
- CURRENT MONITORS #1
- SOC: SERDES1 & 4 INTERFACE
- 13
- 47
- EEPROM
- 81
- CURRENT MONITORS #2
- 14
- SOC: DDR0 - LPDDR4 INTERFACE
- 48
- DUAL PORT FTDI
- 82
- CURRENT MONITORS#1 -INA231
- 15
- SOC: DDR1 - LPDDR4 INTERFACE
- 49
- QUAD PORT FTDI
- 83
- CURRENT MONITORS#2 -INA231
- 16
- SOC: MCU FLASH
- 50
- XDS110 DEBUGGER
- 84
- HARDWARE SCHEMATICS
- 17
- OSPI & ONAND INTERFACE
- 51
- JTAG MIPI 60 CONN
- 18
- SOC: MCU & MAIN GENERAL IOS & CLKS
- 52
- LIN TRANSCEIVER
- 19
- GENERAL IO
- 53
- CAN TRANSCEIVERS #1
- 20
- SOC: GENERAL & USB
- 54
- CAN TRANSCEIVERS #2
- 21
- SOC: MCU  RGMII, MMC & ADC
- 55
- CAN TRANSCEIVERS #3
- 22
- SOC: JTAG & DEBUG
- 56
- USB HUB
- 23
- SOC: USB
- 57
- USB 2.0 TYPE-A CONN
- SOC: ANALOG POWER 1
- 24
- 58
- USB TYPE C 3.1
- 25
- SOC: IO POWER 2
- 59
- MCU GB ETHERNET
- 26
- SOC: DIGITAL POWER 3
- 60
- RGMII1
- 27
- SOC: GROUND & KELVIN SENSING
- 61
- AUDIO I/F CODEC
- 28
- PMIC A
- 62
- AUDIO I/F- STEREO MIC #1
- 29
- HCPS A
- 63
- AUDIO I/F - LINE OUT
- 30
- HCPS B
- 64
- DSI TO eDP BRIDGE
- 31
- SOC LDOS & LOAD SWITCHES
- 65
- DISPLAY PORT INTERFACE
- 32
- SVS MONITOR
- 66
- ADC, RTC, I3C, APPLE AUTH
- 33
- HYPERLINK & CSI CONNECTOR
- 67
- x1LANE PCIe CONN
- GESI CONNECTOR
- 34
- 68
- x4LANE PCIe CONN
- J742S2/TDA4VPE/TDA4APE Evaluation Module
sheet 5
- REVISION HISTORY #1
- VER #
- DATE
- DESCRIPTION OF CHANGES
- AUTHOR
- REVIEWED  BY
- APPROVED  BY
- Updated SOC Symbol into TI Breakout schematics drafted from PROC141E4A.
  Deleted unused sections of the schematics; DDR2, DDR3, ENET-EXP-1, ENET-EXP-2,
  and corresponding SOC power sections
- Mistral Design Team
- 0.1
- 14 DEC 2023
- E1
- 0.2
- 19 DEC 2023
- Deleted SERDES4 Rx testponints.
  Deleted unused 0.1uF caps on:
  VDD_CORE: C869, C987, C871, C956, C924, C771
  VDD_CPU: C964, C961, C903
  VDDSHV0_MCU: C1030
  VDDSHV0: C945
  VDDS_MMC0: C868
  VDDSHV5: C975
  VDDS_DDR: U50155, U50190, C1013, U50173, U50181, C946, U50182, U50180, C1061
  VDDA_0P8_PLL_DDR2: C991, C1076, C1087, FL195
- Mistral Design Team
- 0.3
- 24 JAN 2024
- Updated TI review comments:
  SOC symbol SERDES PCIe clock out section is updated along with removal of symbol documentation
- Mistral Design Team
- E1A
- 0.4
- 16 MAY 2024
- Updated TI comments
- Mistral Design Team
- DNI - U229 and Populated U230
sheet 6
- BLOCK DIAGRAM
sheet 7
- POWER FLOW DIAGRAM
sheet 8
- POWER SEQUENCE
sheet 9
- I2C TREE
sheet 10
- GPIO EXPANDER MAP/TABLE
sheet 11
- DSI
- CSI
sheet 12
- SERDES0
- Dedicated 2L to PCIe4L connector, x2L
  will be resistor muxed with USBC
- Default connected to USBC
- PCIe4L
- USBC
